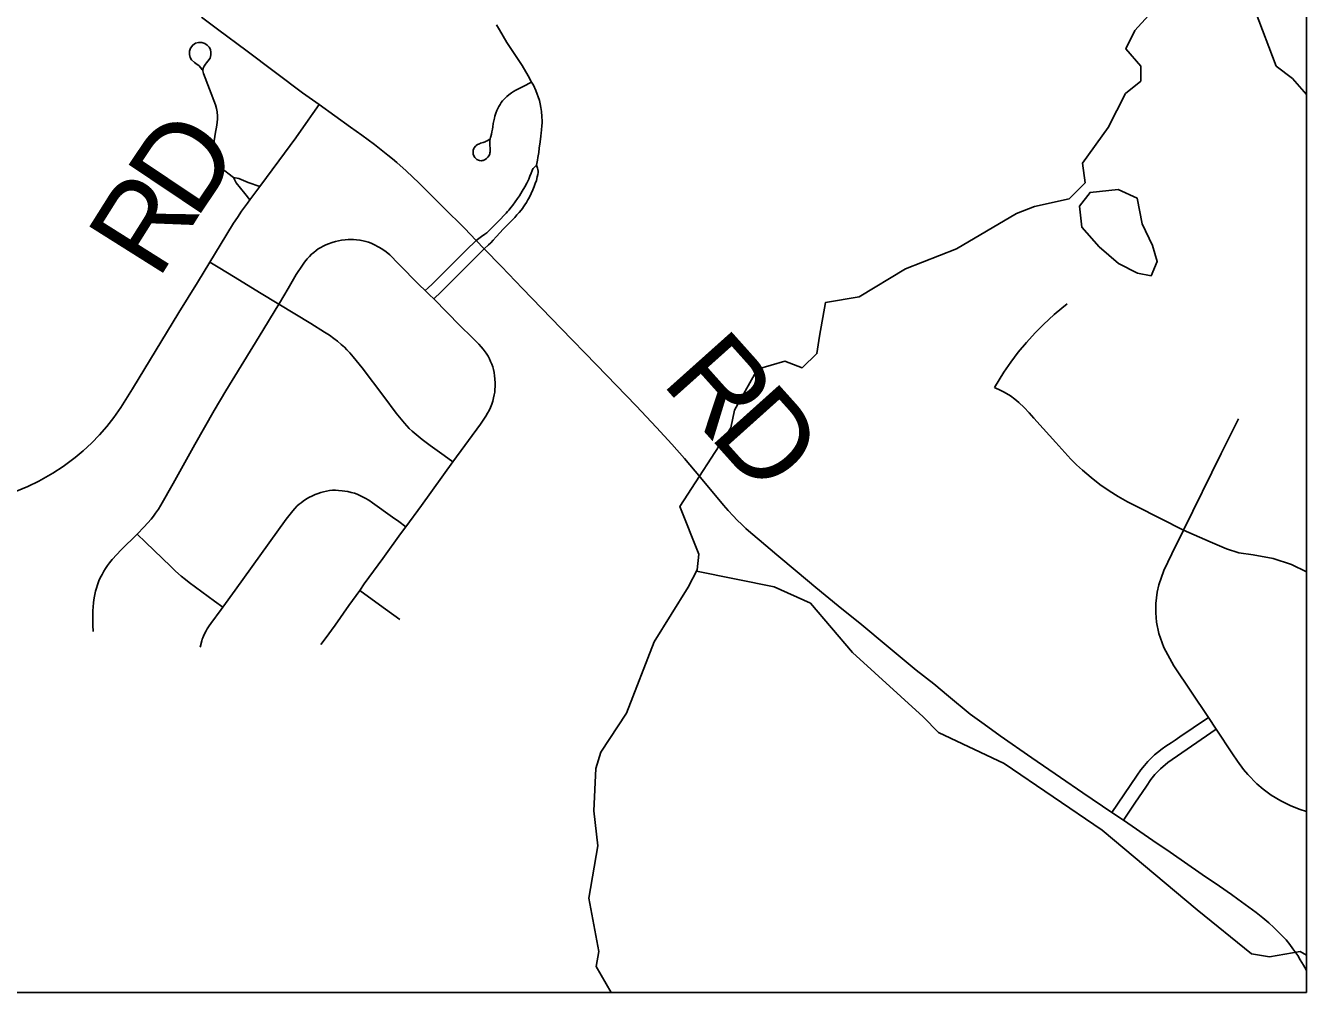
# Model space of a CAD drawing. Extents: x 0 to 34, y 0 to 22.
# Drawn here: x 7.875 to 8.712, y 14.306 to 14.937 of the extents above; entities that cross this region are included whole.
import ezdxf

# ---------------------------------------------------------------- set-up
doc = ezdxf.new("R2010")
doc.units = 0
for name, color, linetype in [('GM_X_Corporation', 7, 'Continuous'), ('GM_X_County_Road', 7, 'Continuous'), ('GM_X_County_Road_Text', 7, 'Continuous'), ('GM_X_Minor_Lake', 7, 'Continuous'), ('GM_X_Minor_River', 7, 'Continuous'), ('GM_X_Township_Road', 7, 'Continuous'), ('GM_X_Township_Road_Text', 7, 'Continuous')]:
    doc.layers.add(name, color=color, linetype=linetype)

msp = doc.modelspace()

# ---------------------------------------------------------------- linework, layer by layer
at = {"layer": 'GM_X_Corporation'}
for points in [[(3.43805, 14.30587), (8.71189, 14.30587), (8.71189, 21.10587)], [(6.3265, 14.36273), (7.02308, 14.30587), (8.71189, 14.30587), (8.71189, 21.02216)]]:
    msp.add_lwpolyline(points, dxfattribs=at)
at = {"layer": 'GM_X_County_Road'}
for points in [[(7.99014, 14.94272), (8.00072, 14.93496), (8.0201, 14.92048), (8.05623, 14.89324), (8.067, 14.88557)], [(8.067, 14.88557), (8.08755, 14.87096), (8.09503, 14.86562), (8.10317, 14.85962), (8.10768, 14.85616), (8.11203, 14.85256), (8.11492, 14.85024), (8.11781, 14.8478), (8.12384, 14.84238), (8.13245, 14.83426), (8.14834, 14.8185), (8.16194, 14.80485), (8.16958, 14.79693)], [(8.16958, 14.79693), (8.17481, 14.79152), (8.18608, 14.77978), (8.19981, 14.76541), (8.22484, 14.73952), (8.24827, 14.71557), (8.27422, 14.68886), (8.28739, 14.67481), (8.29744, 14.66378), (8.30567, 14.65445), (8.31607, 14.64205), (8.33118, 14.62395), (8.33424, 14.62049), (8.33741, 14.61708), (8.34007, 14.61432), (8.3431, 14.61142), (8.34582, 14.6089), (8.3491, 14.60607), (8.35454, 14.60134), (8.36608, 14.59155), (8.3792, 14.58046), (8.39153, 14.57018), (8.406, 14.55834), (8.42145, 14.54593), (8.43748, 14.53253), (8.45713, 14.51634), (8.46847, 14.5073), (8.47817, 14.49924), (8.49239, 14.48765), (8.49683, 14.48428), (8.50143, 14.48091), (8.51196, 14.47343), (8.53267, 14.45894), (8.55133, 14.44614), (8.5658, 14.43619), (8.58484, 14.42336), (8.59234, 14.41827), (8.61158, 14.40515), (8.62286, 14.39735), (8.64385, 14.38291), (8.65513, 14.37521), (8.66288, 14.36969), (8.66715, 14.36673), (8.67192, 14.36336), (8.67916, 14.3581), (8.68343, 14.35457), (8.68729, 14.35128), (8.69058, 14.34823), (8.69346, 14.34544), (8.69559, 14.3433), (8.69864, 14.34009), (8.70102, 14.33706), (8.70308, 14.33434), (8.7062, 14.3299), (8.70793, 14.32719), (8.7099, 14.32366), (8.71189, 14.32011)]]:
    msp.add_lwpolyline(points, dxfattribs=at)
at = {"layer": 'GM_X_Minor_Lake'}
for points in [[(8.61053, 14.77377), (8.6145, 14.78319), (8.61129, 14.79352), (8.60473, 14.80774), (8.60126, 14.82454), (8.58885, 14.83014), (8.57061, 14.82825), (8.56361, 14.81928), (8.56524, 14.80556)], [(8.56524, 14.80556), (8.57661, 14.79266), (8.58926, 14.78186), (8.60159, 14.77548), (8.61053, 14.77377)]]:
    msp.add_lwpolyline(points, dxfattribs=at)
at = {"layer": 'GM_X_Minor_River'}
for points in [[(8.65509, 14.99892), (8.66282, 14.98861), (8.66015, 14.96814), (8.67833, 14.94682), (8.69206, 14.91078), (8.7029, 14.90256), (8.71189, 14.89214)], [(8.60885, 14.94378), (8.59994, 14.93408), (8.59402, 14.92204), (8.60367, 14.91081), (8.60386, 14.90092), (8.59384, 14.89277), (8.58242, 14.87058), (8.56566, 14.84737), (8.56731, 14.83441), (8.55687, 14.82399), (8.5344, 14.81916), (8.52255, 14.81447), (8.48341, 14.79137), (8.45016, 14.77841), (8.41984, 14.76006), (8.39777, 14.75636), (8.39394, 14.73439), (8.3922, 14.72302), (8.38254, 14.71372), (8.37125, 14.71815), (8.35331, 14.71284), (8.33839, 14.68617), (8.33589, 14.67444), (8.30266, 14.62308), (8.31497, 14.59202), (8.31401, 14.58177), (8.3081, 14.57049), (8.2858, 14.53487), (8.26784, 14.48812), (8.25104, 14.46264), (8.2478, 14.45206), (8.24651, 14.42434), (8.24911, 14.40148), (8.24315, 14.3674), (8.24969, 14.33266), (8.24798, 14.32282), (8.25772, 14.30587)], [(8.31361, 14.581), (8.36425, 14.57079), (8.38794, 14.56001), (8.4154, 14.52785), (8.46163, 14.48578), (8.47168, 14.47568), (8.51454, 14.45536), (8.57857, 14.41176), (8.64054, 14.35985), (8.67603, 14.33095), (8.68775, 14.32917), (8.70792, 14.33254), (8.71189, 14.33009)]]:
    msp.add_lwpolyline(points, dxfattribs=at)
at = {"layer": 'GM_X_Township_Road'}
for p in [(8.13643, 14.76418), (8.14202, 14.75866)]:
    msp.add_line(p, (8.13924, 14.76138), dxfattribs=at)
for points in [[(8.18299, 14.93761), (8.1848, 14.9344), (8.18961, 14.92625), (8.19959, 14.91114), (8.20371, 14.9044), (8.20587, 14.90035)], [(8.01117, 14.83805), (8.00751, 14.84074), (8.00533, 14.84249), (8.00332, 14.84466), (8.00196, 14.84644), (8.00075, 14.84858), (7.99975, 14.85054), (7.99899, 14.8529), (7.99843, 14.8549), (7.99832, 14.85696), (7.99835, 14.85917), (7.9986, 14.86189), (7.99901, 14.86485), (7.99942, 14.86764), (7.99983, 14.8697), (8.00016, 14.87216), (8.00049, 14.87414), (8.00065, 14.87611), (8.00065, 14.87816), (8.00041, 14.88096), (8, 14.8831), (7.99934, 14.8854), (7.99161, 14.90595), (7.9912, 14.90759), (7.99136, 14.9094), (7.99194, 14.91072), (7.99276, 14.91195), (7.99358, 14.91293), (7.99448, 14.91392), (7.9958, 14.91589), (7.99629, 14.91811), (7.99629, 14.91968), (7.99613, 14.92148), (7.99522, 14.92313), (7.99391, 14.92444), (7.99235, 14.92543), (7.99038, 14.92617), (7.98832, 14.92617), (7.98643, 14.92568), (7.98454, 14.92444), (7.98314, 14.92255), (7.9824, 14.92058), (7.9824, 14.91836), (7.98281, 14.91647), (7.98372, 14.91491), (7.98577, 14.91302), (7.98733, 14.91187), (7.9884, 14.91105), (7.98988, 14.90965), (7.99079, 14.90833)], [(8.17848, 14.86301), (8.17683, 14.86199), (8.17613, 14.86162), (8.17544, 14.86129), (8.17482, 14.86104), (8.17412, 14.8608), (8.1733, 14.86055), (8.17256, 14.86034), (8.17174, 14.86006), (8.17112, 14.85981), (8.17054, 14.85952), (8.16956, 14.85886), (8.16911, 14.85841), (8.16837, 14.85747), (8.16808, 14.85689), (8.16775, 14.85578), (8.16763, 14.85467), (8.16763, 14.85397), (8.16773, 14.8533), (8.16808, 14.85211), (8.16871, 14.85104), (8.16959, 14.85015), (8.17018, 14.84972), (8.17116, 14.8493), (8.17183, 14.84911), (8.17302, 14.84898), (8.17366, 14.84905), (8.1743, 14.84919), (8.17546, 14.84965), (8.1765, 14.85034), (8.17737, 14.85123), (8.17804, 14.85228), (8.17847, 14.85341), (8.17864, 14.85405), (8.17873, 14.85469), (8.17875, 14.85582), (8.17868, 14.85738), (8.17856, 14.85866), (8.17856, 14.8608), (8.17865, 14.86219), (8.17881, 14.8633), (8.17897, 14.86412), (8.17918, 14.86487), (8.17955, 14.86628), (8.17991, 14.8678), (8.18024, 14.86965), (8.18049, 14.87113), (8.18082, 14.87319), (8.18115, 14.87507), (8.18152, 14.87672), (8.18193, 14.87816), (8.18258, 14.88005), (8.1832, 14.88169), (8.18386, 14.88313), (8.18444, 14.88428), (8.18521, 14.88568), (8.18604, 14.88695), (8.18694, 14.88814), (8.18764, 14.88897), (8.18854, 14.88991), (8.18966, 14.89089), (8.19101, 14.89201), (8.19269, 14.8932), (8.1941, 14.8941), (8.19565, 14.89505), (8.19722, 14.89591), (8.20026, 14.89748), (8.20587, 14.90035)], [(8.20587, 14.90035), (8.20699, 14.8982), (8.20863, 14.89474), (8.20958, 14.89248), (8.21024, 14.89067), (8.21094, 14.8882), (8.21143, 14.88603), (8.21188, 14.88381), (8.21229, 14.88113), (8.21258, 14.87789), (8.21267, 14.87476), (8.21267, 14.87345), (8.21262, 14.87197), (8.21237, 14.86889), (8.21217, 14.86708), (8.21196, 14.86503), (8.21147, 14.86129), (8.21089, 14.85714), (8.21048, 14.85422), (8.20999, 14.85113), (8.2097, 14.84925), (8.20932, 14.84719), (8.20909, 14.84601)], [(8.02187, 14.82346), (8.02827, 14.83213), (8.04078, 14.8488), (8.05187, 14.86393), (8.05993, 14.87544), (8.06297, 14.87979), (8.067, 14.88557)], [(8.20909, 14.84601), (8.20797, 14.84502), (8.20732, 14.84436), (8.20687, 14.84379), (8.20654, 14.84325), (8.20623, 14.8426), (8.20563, 14.84087), (8.2048, 14.83877), (8.204, 14.83682), (8.2027, 14.83429), (8.20142, 14.83189), (8.19975, 14.82907), (8.19787, 14.82609), (8.19662, 14.82426), (8.19519, 14.82221), (8.19357, 14.82003), (8.19243, 14.81855), (8.19099, 14.8167), (8.19017, 14.81571), (8.18929, 14.81475), (8.18409, 14.80926), (8.17763, 14.80293), (8.17653, 14.80195), (8.17537, 14.80104), (8.17323, 14.79948), (8.16958, 14.79693)], [(8.20909, 14.84601), (8.20979, 14.84416), (8.20999, 14.84329), (8.21011, 14.84222), (8.21011, 14.8412), (8.20994, 14.83996), (8.20958, 14.8384), (8.20896, 14.83613), (8.20826, 14.834), (8.2076, 14.83219), (8.20666, 14.82993), (8.20563, 14.82766), (8.20419, 14.82479), (8.20337, 14.82331), (8.20243, 14.82166), (8.20147, 14.82015), (8.20065, 14.81891), (8.19987, 14.81784), (8.19897, 14.81661), (8.19765, 14.81504), (8.1963, 14.81353), (8.19482, 14.81193), (8.18701, 14.80407), (8.18524, 14.80214), (8.18278, 14.79931), (8.18079, 14.79703), (8.17916, 14.79536), (8.17772, 14.79404), (8.17481, 14.79152)], [(8.02827, 14.83213), (8.02066, 14.83484), (8.01454, 14.83739), (8.01117, 14.83805)], [(8.02187, 14.82346), (8.01846, 14.82763), (8.0129, 14.83443), (8.01117, 14.83805)], [(7.99574, 14.7828), (8.00243, 14.79381), (8.01125, 14.80809), (8.01373, 14.81189), (8.01636, 14.81592), (8.02031, 14.82134), (8.02187, 14.82346)], [(8.04077, 14.7553), (8.0411, 14.75585), (8.0468, 14.76547), (8.05205, 14.77463), (8.05615, 14.78086), (8.05751, 14.78278), (8.05917, 14.7848), (8.06075, 14.78647), (8.06219, 14.78793), (8.06355, 14.7891), (8.06507, 14.7903), (8.06651, 14.79133), (8.06819, 14.79232), (8.06976, 14.79317), (8.07151, 14.79402), (8.07329, 14.79474), (8.07557, 14.79557), (8.07773, 14.79617), (8.07978, 14.79668), (8.08176, 14.79704), (8.08398, 14.79732), (8.08595, 14.79749), (8.08779, 14.79757), (8.08953, 14.79753), (8.09151, 14.79737), (8.09368, 14.79708), (8.09581, 14.79669), (8.09762, 14.79625), (8.0994, 14.79571), (8.10112, 14.79506), (8.10286, 14.79432), (8.10613, 14.79253), (8.10798, 14.79141), (8.11081, 14.78947), (8.11317, 14.78746), (8.11884, 14.78171), (8.13252, 14.768), (8.13643, 14.76418)], [(8.13643, 14.76418), (8.13836, 14.76603), (8.14084, 14.76842), (8.16308, 14.79048), (8.16958, 14.79693)], [(8.14202, 14.75866), (8.14676, 14.76334), (8.15309, 14.76959), (8.16427, 14.78077), (8.16838, 14.78496), (8.17481, 14.79152)], [(7.86933, 14.63324), (7.87675, 14.63631), (7.88397, 14.63978), (7.89309, 14.64498), (7.89982, 14.64936), (7.90782, 14.65515), (7.91305, 14.65946), (7.91845, 14.66452), (7.92357, 14.66987), (7.9284, 14.67548), (7.93296, 14.68131), (7.93754, 14.6879), (7.9451, 14.69998), (7.97554, 14.74983), (7.98759, 14.76939), (7.99574, 14.7828)], [(7.99574, 14.7828), (8.00111, 14.77951), (8.01224, 14.7727), (8.02814, 14.76295), (8.04077, 14.7553)], [(8.15447, 14.65234), (8.17252, 14.67699), (8.17599, 14.68215), (8.17714, 14.68414), (8.17808, 14.68595), (8.17894, 14.68784), (8.17977, 14.68996), (8.18042, 14.69194), (8.18104, 14.69411), (8.18145, 14.69598), (8.18176, 14.69776), (8.18194, 14.69955), (8.18205, 14.70147), (8.18203, 14.70366), (8.1819, 14.70644), (8.1817, 14.70847), (8.18132, 14.71057), (8.18096, 14.71254), (8.18046, 14.71435), (8.17981, 14.71615), (8.17911, 14.71782), (8.1783, 14.7195), (8.1774, 14.72123), (8.17609, 14.72329), (8.1742, 14.72583), (8.17286, 14.72746), (8.17144, 14.72907), (8.1671, 14.7335), (8.15907, 14.74137), (8.1506, 14.74984), (8.14202, 14.75866)], [(7.94828, 14.6051), (7.95281, 14.60979), (7.95727, 14.61495), (7.95879, 14.61681), (7.9603, 14.61888), (7.96207, 14.62141), (7.96372, 14.62407), (7.97175, 14.63808), (7.98587, 14.66365), (7.99844, 14.68581), (8.00606, 14.69862), (8.02786, 14.7341), (8.04077, 14.7553)], [(8.04077, 14.7553), (8.06162, 14.74267), (8.0706, 14.73709), (8.07376, 14.73497), (8.07673, 14.73284), (8.0791, 14.73103), (8.08157, 14.72895), (8.08354, 14.72725), (8.0852, 14.72555), (8.08708, 14.72355), (8.08935, 14.72094), (8.09513, 14.71363), (8.10928, 14.69495), (8.11749, 14.68409), (8.12283, 14.67752), (8.12596, 14.67415), (8.12794, 14.67225), (8.1304, 14.67012), (8.13434, 14.667), (8.13957, 14.66295), (8.14868, 14.65646), (8.15447, 14.65234)], [(8.50809, 14.70088), (8.51431, 14.71091), (8.5188, 14.71738), (8.52372, 14.72386), (8.52908, 14.73031), (8.53471, 14.73652), (8.54011, 14.74198), (8.54718, 14.74844), (8.5521, 14.75263), (8.55556, 14.75558)], [(8.71189, 14.58048), (8.70214, 14.58528), (8.69017, 14.58915), (8.67709, 14.59153), (8.66778, 14.59296), (8.65974, 14.59544), (8.64903, 14.60007), (8.63161, 14.60769), (8.60121, 14.62314), (8.59497, 14.6263), (8.58889, 14.62975), (8.58297, 14.63347), (8.57708, 14.63757), (8.57125, 14.64206), (8.56564, 14.64683), (8.56178, 14.65042), (8.55808, 14.65408), (8.54816, 14.66494), (8.54004, 14.674), (8.53395, 14.68077), (8.53073, 14.68436), (8.5276, 14.68778), (8.52416, 14.69102), (8.52139, 14.69327), (8.51853, 14.69534), (8.51449, 14.69781), (8.5124, 14.69892), (8.50809, 14.70088)], [(8.71189, 14.42404), (8.70786, 14.42526), (8.70183, 14.42762), (8.69521, 14.43087), (8.68894, 14.4347), (8.68369, 14.43854), (8.67948, 14.44214), (8.67365, 14.44806), (8.67075, 14.45152), (8.66688, 14.45682), (8.66361, 14.46172), (8.65289, 14.47782), (8.64789, 14.48534), (8.62539, 14.51916), (8.61868, 14.53101), (8.61548, 14.54031), (8.61405, 14.54755), (8.61353, 14.55379), (8.61359, 14.55983), (8.61447, 14.56716), (8.61553, 14.57197), (8.61877, 14.58126), (8.62404, 14.59218), (8.63161, 14.60769), (8.65633, 14.65781), (8.66745, 14.68042)], [(8.12371, 14.60991), (8.13388, 14.62374), (8.15447, 14.65234)], [(8.00414, 14.55741), (8.01229, 14.56847), (8.04562, 14.6148), (8.0498, 14.62028), (8.05121, 14.62192), (8.05281, 14.62356), (8.05397, 14.62463), (8.05524, 14.62565), (8.05668, 14.62668), (8.05828, 14.62775), (8.06029, 14.62894), (8.06285, 14.63021), (8.06457, 14.63096), (8.06638, 14.63166), (8.06827, 14.63236), (8.07003, 14.63284), (8.07192, 14.63322), (8.07381, 14.63351), (8.07591, 14.63372), (8.07772, 14.63375), (8.0797, 14.63367), (8.08208, 14.63349), (8.08389, 14.63322), (8.08585, 14.6329), (8.08791, 14.6324), (8.09015, 14.63176), (8.0919, 14.63113), (8.09371, 14.63034), (8.09548, 14.62952), (8.09712, 14.62867), (8.09951, 14.62722), (8.10191, 14.62564), (8.11504, 14.61618), (8.11906, 14.61328), (8.12371, 14.60991)], [(8.09356, 14.56833), (8.09659, 14.57255), (8.10861, 14.58915), (8.12027, 14.60523), (8.12371, 14.60991)], [(7.91941, 14.54151), (7.91929, 14.54562), (7.9192, 14.54957), (7.91918, 14.55245), (7.91924, 14.55516), (7.91941, 14.55742), (7.91965, 14.5605), (7.92006, 14.56357), (7.92048, 14.5658), (7.92097, 14.56782), (7.92158, 14.56991), (7.92227, 14.57197), (7.92323, 14.57452), (7.92416, 14.57657), (7.92529, 14.57879), (7.92645, 14.58097), (7.92754, 14.58274), (7.92883, 14.58462), (7.93018, 14.58636), (7.93196, 14.58847), (7.93786, 14.59486), (7.94828, 14.6051)], [(7.94828, 14.6051), (7.95367, 14.59988), (7.97013, 14.5839), (7.97333, 14.58089), (7.97699, 14.57767), (7.97974, 14.57538), (7.98228, 14.57342), (7.99878, 14.56134), (8.00414, 14.55741)], [(8.06809, 14.53305), (8.07095, 14.53672), (8.07755, 14.54573), (8.08645, 14.55844), (8.09356, 14.56833)], [(8.09356, 14.56833), (8.0994, 14.56412), (8.11047, 14.55616), (8.11978, 14.54943)], [(7.98948, 14.53137), (7.99043, 14.5354), (7.99071, 14.53647), (7.99104, 14.53742), (7.99149, 14.53848), (7.99249, 14.54039), (7.9933, 14.54198), (7.994, 14.54321), (7.99524, 14.54518), (7.9963, 14.54674), (8.00308, 14.55598), (8.00414, 14.55741)], [(8.64789, 14.48534), (8.63801, 14.47867), (8.62933, 14.47281), (8.62613, 14.47065), (8.62347, 14.46886), (8.62004, 14.46655), (8.61771, 14.46491), (8.61463, 14.46252), (8.61279, 14.46095), (8.61004, 14.45838), (8.6084, 14.45669), (8.60613, 14.45413), (8.60385, 14.45129), (8.60129, 14.44766), (8.59672, 14.44091), (8.58484, 14.42336)], [(8.59234, 14.41827), (8.59984, 14.42953), (8.60744, 14.44058), (8.6103, 14.44482), (8.61296, 14.44817), (8.61661, 14.45192), (8.62144, 14.45606), (8.63683, 14.46662), (8.65289, 14.47782)]]:
    msp.add_lwpolyline(points, dxfattribs=at)

# ---------------------------------------------------------------- texts
at = {"layer": 'GM_X_County_Road_Text'}
for s, rotation, p in [('R', 311.79691, (8.28991, 14.70403)), ('D', 311.88948, (8.32108, 14.66917))]:
    msp.add_text(s, height=0.05682, rotation=rotation, dxfattribs=at).set_placement(p)
at = {"layer": 'GM_X_Township_Road_Text'}
for s, rotation, p in [('D', 56.17252, (7.98642, 14.80958)), ('R', 57.80555, (7.96179, 14.77045))]:
    msp.add_text(s, height=0.05682, rotation=rotation, dxfattribs=at).set_placement(p)

doc.saveas('drawing.dxf')
